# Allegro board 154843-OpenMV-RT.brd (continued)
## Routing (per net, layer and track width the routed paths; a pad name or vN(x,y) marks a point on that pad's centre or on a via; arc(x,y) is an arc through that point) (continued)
N169826: length 1.1
  TOP w0.152: U1.F13 v2(16.48,26.36)
  BOTTOM w0.152: R3.2 16.43,26.42 v2(16.48,26.36)
N229181: length 3.7
  TOP w0.254: U1.P8 22.88,22.79 23.23,22.44 v1(23.23,21.92)
  BOTTOM w0.305: v1(23.23,21.92) 23.34,21.92 23.75,21.51 C22.1 C19.1
N229229: length 12.4
  TOP w0.152: U1.P11 22.32,24.74 23.24,25.65 23.24,27.3 v2(23.75,27.81)
  BOTTOM w0.152: v2(23.75,27.81) 25.6,27.81 25.88,28.08 R8.1 R7.1 26.65,29.17 C42.1 26.97,29.77 26.97,32.11 26.81,32.27 Y1.3
N229241:
  vias: v2(20.7,17.4) v2(21.03,17.91)
N229269: length 3.5
  TOP w0.254: v2(22.86,24.39) 22.31,24.39 U1.P10
  BOTTOM w0.305: C24.1 C23.1 v2(22.86,24.39)
N229297: length 11.6
  TOP w0.152: v2(23.11,27.81) 22.86,27.56 22.86,25.81 22.11,25.06 21.68,25.06 U1.N11
  BOTTOM w0.152: v2(23.11,27.81) 23.55,27.38 25.6,27.38 26.16,27.94 27.14,27.94 27.4,28.19 R7.2 27.4,29.17 C43.1 27.54,30.08 Y1.1
N229465: length 3.7
  TOP w0.191: U1.M10 21.03,24.41 v2(21.03,25.06)
  BOTTOM w0.254: v2(21.03,25.06) 21.22,25.25 22.15,25.25 23.07,26.17 C25.1
N229469: length 9.6
  TOP w0.152: v1(25.02,20.57) 24,21.59 24,22.73 22.98,23.76 21.68,23.76 U1.N9
  BOTTOM w0.152: v1(25.02,20.57) 25.12,20.57 25.61,20.09 C44.1 27.41,20.09 27.56,19.93 Y2.1
N229477: length 8.8
  TOP w0.152: U1.K3 v2(19.73,19.21)
  BOTTOM w0.152: v2(19.73,19.21) 19.84,19.1 22.07,19.1 22.23,18.95 22.23,18.67 23.37,17.53 25.31,17.53 25.69,17.14 C46.1 R9.1
N229533: length 8.8
  TOP w0.152: v1(24.38,20.57) 23.7,21.26 23.7,22.53 22.79,23.44 U1.P9
  BOTTOM w0.152: Y2.2 27.56,20.6 27.41,20.45 26.19,20.45 25.78,20.86 C45.1 25.5,20.86 25.32,21.03 24.84,21.03 v1(24.38,20.57)
N236415:
  vias: v1(34.04,31.37) v1(34.04,30.48)
N236477: length 1.9
  TOP w0.152: J2.4 v1(30.99,27.96)
  BOTTOM w0.152: R32.1 30.97,27.94 v1(30.99,27.96)
N236509: length 6.5
  TOP w0.15: J2.3 28.98,27.3 28.9,27.23 U3.4 27.35,27.23 26.72,26.59 v2(26.46,26.59)
  BOTTOM w0.15: v2(26.46,26.59) 27.13,26.59 27.94,25.78 R11.1
N236553: length 7.5
  TOP w0.15: v2(26.46,25.96) 26.74,25.96 27.38,25.33 U3.3 27.52,26.04 27.86,26.39 28.27,26.39 28.77,26.89 29.04,26.89 29.28,26.65 J2.2
  BOTTOM w0.15: R12.1 27.14,24.76 27.61,25.23 27.61,25.64 26.99,26.26 26.7,26.26 26.46,26.03 v2(26.46,25.96)
N246574: length 11.6
  TOP w0.305: v2(18.16,34.33) 18.16,33.1 18.8,32.46 18.8,32.18 19.1,31.88 20.04,31.88 20.27,32.11 20.27,33.76 v2(20.5,33.99) ; U5.B3 v2(18.58,36.07) ; U5.A1 19.78,35.7 20.12,35.36 v2(20.12,35.31)
  BOTTOM w0.305: v2(20.5,33.99) 20.78,34.26 C59.1 20.42,34.68 20.12,34.98 v2(20.12,35.31) ; v2(18.58,36.07) 18.56,36.05 C64.1 18.56,34.74 v2(18.16,34.33) 18.03,34.21 R20.2
N246626: length 4.1
  TOP w0.188: U5.E3 17.78,39.12 17.78,39.64 18.09,39.95
  TOP w0.305: 18.09,39.95 18.14,40.01 18.92,40.01 19.94,41.02 C60.1
N246706: length 2.4
  TOP w0.152: U5.A3 18.18,35.58 17.14,34.54 C61.1
N246726: length 2.9
  TOP w0.188: U5.B2 19.38,36.07 19.38,35.13
  TOP w0.305: C62.1 19.56,34.95 19.38,35.13
N257264: length 5.3
  TOP w0.152: U6.10 5.28,22.15 5.66,21.77 6.02,21.77 6.32,22.07 6.32,22.56 6.5,22.73 8.26,22.73 8.39,22.86 C63.1
N263637: length 10.3
  TOP w0.152: R13.1 3.42,34.16 4.57,35.31 4.57,39.42 D3.2
N263641: length 6.3
  TOP w0.152: D2.2 1.31,27.64 1.46,27.48 5,27.48 5.66,28.14 RN2.8
N263645: length 4.7
  TOP w0.152: RN2.7 5.94,28.94 4.75,30.12 4.17,30.12 3.01,31.28 D2.3
N263649: length 8.1
  TOP w0.152: D2.4 1.31,32.51 1.57,32.77 3.56,32.77 3.94,32.38 3.94,30.99 4.42,30.51 5,30.51 5.77,29.74 RN2.6
N263673: length 2.3
  TOP w0.152: v1(2.67,34.54) 2.67,34.54 R13.2
  BOTTOM w0.152: Q1.3 v1(2.67,34.54)
N263791: length 4
  TOP w0.152: RN2.5 6.35,31.62 R19.1 5.04,31.62 v1(4.57,31.16)
  BOTTOM w0.152: Q1.1 v1(4.57,31.16)
N264381: length 21.1
  TOP w0.152: D1.2 D3.1
N332353: length 8.7
  TOP w0.152: v1(27.81,11.3) 27.56,11.05 26.53,11.05
  BOTTOM w0.152: R15.1 26.92,10.08 27.07,9.93 28.24,9.93 28.39,10.08 28.39,10.9 29.03,11.54 29.03,12.4 28.88,12.55 28.47,12.55 28.35,12.42 28.35,11.84 v1(27.81,11.3)
N332366: length 6.1
  TOP w0.152: v2(17.04,13) 17.27,13 17.86,13.59 U4.2
  BOTTOM w0.152: v2(17.04,13) 16.81,12.78 16.81,10.57 17.25,10.13 R16.1
N332379: length 5
  TOP w0.152: U4.3 18.16,12.32 v1(17.75,11.91)
  BOTTOM w0.152: v1(17.75,11.91) 17.37,11.91 17.22,11.76 17.22,10.79 17.4,10.62 18.31,10.62 R17.1
N332392: length 2.6
  TOP w0.152: U4.7 27.3,13.59 v1(27.81,13.08)
  BOTTOM w0.152: R18.1 27.3,13.59 v1(27.81,13.08)
N670164:
  vias: v1(22.35,2.54) v1(22.35,1.52) v1(23.37,2.54) v1(23.37,1.52)
N7344830: length 21.4
  TOP w0.152: U1.L4 20.4,19.84 21.5,19.84 21.67,19.67 21.67,19.41 21.88,19.21 22.11,19.21 22.61,18.71 22.61,14.53 22.46,14.37 21.54,14.37 21.39,14.22 21.39,13.92 21.54,13.76 22.35,13.76 22.5,13.61 22.5,13.36 22.35,13.2 21.54,13.2 21.39,13.05 21.39,12.75 21.54,12.59 21.62,12.59 21.77,12.44 21.77,12.14 21.62,11.99 21.16,11.99 21.01,11.83 21.01,11.53 21.16,11.38 21.44,11.38 21.94,10.87 24.05,10.87 24.26,10.67 24.51,10.67 24.64,10.79 v1(24.64,11.3)
  BOTTOM w0.152: v1(24.64,11.3) 24.64,11.14 24.86,10.92 25.24,10.92 26.17,11.85 R10.1

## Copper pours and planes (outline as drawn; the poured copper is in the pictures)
GND on TOP: 14.73,7.75 13.84,7.75 13.72,7.87 13.72,9.4 13.84,9.53 14.73,9.53 14.86,9.4 14.86,7.87
GND on TOP: 14.99,4.19 16.51,4.19 16.64,4.06 16.64,1.02 16.51,0.89 14.99,0.89 14.86,1.02 14.86,4.06
GND on TOP: 18.16,43.18 19.43,43.18 19.56,43.05 19.56,41.4 18.92,40.77 18.16,40.77 18.03,40.89 18.03,43.05
GND on TOP: 9.78,13.84 9.78,12.83 9.02,12.83 8.76,13.08 6.86,13.08 6.73,13.21 6.73,15.11 6.86,15.24 8.38,15.24
GND on BOTTOM: 21.72,20.83 24,20.83 24.64,20.19 25.15,20.19 25.27,20.07 25.27,19.68 25.4,19.56 26.04,19.56 26.16,19.43 26.16,18.67 26.04,18.54 25.4,18.54 24.77,19.18 23.5,19.18 23.24,19.43 20.95,19.43 20.95,19.94 21.59,19.94 21.72,20.07
GND on BOTTOM: 17.78,43.18 19.43,43.18 19.56,43.05 19.56,40.77 19.43,40.64 17.53,40.64 17.4,40.77 17.4,41.27 17.65,41.53 17.65,43.05
GND on BOTTOM: 17.53,7.37 18.92,7.37 19.05,7.24 19.05,6.1 19.3,5.84 19.3,5.08 19.18,4.95 18.41,4.95 17.4,5.97 17.4,7.24
GND on BOTTOM: 30.86,31.62 32,31.62 32.13,31.5 32.13,30.35 32,30.23 30.86,30.23 30.73,30.35 30.73,31.5
GND on BOTTOM: 18.16,17.4 20.19,17.4 20.57,17.02 20.57,15.24 20.45,15.11 17.65,15.11 17.53,15.24 17.53,16.76
GND on GND02: 0.51,0.51 0.51,42.16 2.29,43.94 5.28,43.94 4.01,45.21 4.27,45.47 31.04,45.47 31.04,43.94 33.4,43.94 35.05,42.29 35.05,0.51
VDD_3V3 on TOP: 20.19,6.22 18.92,4.95 18.92,1.02 18.8,0.89 17.65,0.89 17.53,1.02 17.53,4.45 15.11,6.86 15.11,9.4 20.19,9.4
VDD_3V3 on TOP: 7.49,12.57 9.91,12.57 10.03,12.45 10.03,11.05 9.91,10.92 7.49,10.92 7.37,11.05 7.37,12.45
VDD_3V3 on TOP: 15.49,43.18 16.89,43.18 17.02,43.05 17.02,41.53 16.89,41.4 15.49,41.4 15.37,41.53 15.37,43.05
VDD_3V3 on TOP: 25.86,15.88 27.81,15.88 27.94,15.75 27.94,14.61 27.81,14.48 25.65,14.48 25.58,14.55 25.58,15.01 25.81,15.24 25.81,15.82
VDD_3V3 on BOTTOM: 15.49,43.18 17.02,43.18 17.14,43.05 17.14,40.77 17.02,40.64 15.49,40.64 15.37,40.77 15.37,43.05
VDD_3V3 on BOTTOM: 10.03,13.28 10.03,11.56 9.91,11.43 9.02,11.43 8.89,11.56 8.89,11.94 9.14,12.19 9.14,13.28 9.17,13.31 10.01,13.31
VDD_3V3 on POWER03: 1.02,1.02 1.02,43.43 3.91,43.43 2.06,45.29 2.06,45.47 31.09,45.47 31.09,43.84 30.68,43.43 34.54,43.43 34.54,2.54 33.02,1.02 ; 1 cut-out
VDD_SOC_IN on BOTTOM: 17.02,18.67 17.02,19.46 17.09,19.53 17.09,20.19 16.97,20.32 16.51,20.32 16.38,20.45 16.38,21.46 16.26,21.59 16.26,23.88 16.38,24 17.14,24 17.27,23.88 17.27,22.86 17.4,22.73 17.53,22.73 17.65,22.61 17.65,21.84 17.53,21.72 17.53,21.08 17.65,20.95 17.91,20.95 18.29,21.34 18.54,21.34 18.67,21.21 18.67,20.45 17.78,19.56 17.78,18.47 16.59,17.27 13.46,17.27 13.34,17.4 13.34,18.03 13.46,18.16 16.51,18.16
VDD_SOC_IN on BOTTOM: 24.89,14.35 25.02,14.22 25.02,12.95 24.89,12.83 21.08,12.83 20.45,12.19 17.65,12.19 17.53,12.32 17.53,14.1 17.65,14.22 20.45,14.22 20.57,14.35
VDD_SOC_IN on POWER03: 13.36,16.92 13.36,17.73 13.41,17.78 16.66,17.78 16.92,18.03 16.92,21.46 16.74,21.64 16.31,21.64 16.28,21.67 16.28,23.9 16.38,24 18.54,24 18.67,23.88 18.67,23.11 19.3,22.48 19.3,17.53 21.08,15.75 21.08,12.83 20.95,12.7 19.23,12.7 19.13,12.8 19.13,15.67 17.93,16.87 13.41,16.87
EP on BOTTOM: 4.32,25.27 5.84,25.27 5.97,25.15 5.97,23.88 5.84,23.75 4.32,23.75 4.19,23.88 4.19,25.15
Net_2 on BOTTOM (solid shape): outline of 388 points within 71.62,0.5 75.62,91.45
Net_3 on TOP (solid shape): outline of 388 points within 71.62,0.5 75.62,91.45
Net_4 on BOTTOM (solid shape): outline of 388 points within -4.5,0.5 -0.5,91.45
Net_5 on TOP (solid shape): outline of 388 points within -4.5,0.5 -0.5,91.45
RAW_5V on BOTTOM: 21.97,3.17 21.84,3.3 21.84,4.95 24,7.11 25.27,7.11 25.4,6.99 25.4,5.71 25.65,5.46 28.57,5.46 28.96,5.84 34.8,5.84 34.92,5.71 34.92,4.19 34.8,4.06 25.02,4.06 24.13,3.17
USB_5V on TOP: 25.02,23.11 27.05,23.11 28.19,21.97 28.19,20.42 29.21,19.41 29.21,10.54 26.16,7.49 23.88,7.49 23.11,6.73 21.72,6.73 21.59,6.86 21.59,7.87 21.72,8 22.48,8 22.99,8.51 25.53,8.51 28.19,11.18 28.19,18.64 26.67,20.17 26.67,21.46 25.91,22.23 25.02,22.23 24.89,22.35 24.89,22.99
USB_5V on BOTTOM: 20.95,4.83 20.95,3.56 20.83,3.43 19.68,3.43 19.56,3.56 19.56,7.75 19.68,7.87 22.86,7.87 22.99,7.75 22.99,6.86
N229241 on TOP: 21.21,17.53 20.83,17.14 20.57,17.14 20.45,17.27 20.45,18.16 20.7,18.41 20.7,18.67 20.57,18.8 20.57,19.05 20.83,19.05 21.21,18.67
N229241 on BOTTOM: 21.72,17.27 24.89,17.27 25.02,17.14 25.02,15.88 24.89,15.75 21.08,15.75 21.08,16.64 20.45,17.27 20.45,18.03 20.57,18.16 21.21,18.16 21.34,18.03 21.34,17.65
N236415 on TOP: 31.62,32.77 34.8,32.77 34.92,32.64 34.92,22.23 34.8,22.1 31.62,22.1 31.5,22.23 31.5,32.64
N236415 on BOTTOM: 33.02,31.62 34.16,31.62 34.29,31.5 34.29,30.35 34.16,30.23 33.02,30.23 32.89,30.35 32.89,31.5
N236589 on TOP: 29.16,26.29 30.48,26.29 30.61,26.16 30.61,25.91 30.48,25.78 29.97,25.78 29.72,25.53 29.72,24.13 29.08,23.5 26.29,23.5 26.04,23.75 24.77,23.75 24.51,24 24.51,25.78 24.64,25.91 26.04,25.91 26.16,25.78 26.16,25.15 26.8,24.51 28.19,24.51 28.45,24.77 28.45,25.58
N670164 on TOP: 23.5,3.68 23.62,3.56 23.62,1.02 23.5,0.89 20.07,0.89 19.94,1.02 19.94,3.56 20.07,3.68
N670164 on BOTTOM: 23.62,1.4 23.5,1.27 20.95,1.27 20.83,1.4 20.83,2.67 20.95,2.79 23.5,2.79 23.62,2.67

Small or netless copper shapes (teardrops, artwork), in the pictures only: 2 on TOP

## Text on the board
BOTTOM: 154843-OPENMV-RT ARTWORK BOTTOM
Package Geometry/Pastemask Bottom: 154843-OPENMV-RT PASTEMASK BOTTOM
Ref Des/Silkscreen Bottom: A | VIN | P3 | 3.3V | P0 | P1 | P2 | P4 | P5 | P6 | SWO | SWC | SWD | RST | GND | CTX | FSIN | P9 | P8 | P7 | V1.0 | Built By NXP | 154843-OPENMV-RT SILKSCREEN BOTTOM
User.Comments: 154843-OPENMV-RT SOLDMASK TOP | 154843-OPENMV-RT SOLDMASK BOTTOM
TOP: 154843-OPENMV-RT ARTWORK TOP
Package Geometry/Pastemask Top: 154843-OPENMV-RT PASTEMASK TOP
Ref Des/Silkscreen Top: P0 | Pin List | P4=TXD/SCL | P5=RXD/SDA | P7=SERVO1 | P8=SERVO2 | P9=SERVO3 | P0=MOSI | P1=MISO | P2=SCLK | P6=ADC | P3=SS | GND | VIN | P1 | P2 | P3 | P4 | P5 | P6 | 3.3V | SWO | SWC | SWD | RST | CTX | FSIN | P9 | P8 | P7 | 154843-OPENMV-RT SILKSCREEN TOP
GND02: 154843-OPENMV-RT GROUND PLANE02
POWER03: 154843-OPENMV-RT POWER PLANE03
DIMENSION: 154843-OPENMV-RT DRILL CHART | 1--Gerber TOP | 2--GROUND PLANE02 | 3--POWER PLANE03 | 4--Gerber BOTTOM
COMPVAL_TYPE_TOP: LAYER 1  TOP SIDE           1 oz. | LAYER 2  INTERNAL 1      2 oz. | LAYER 3  INTERNAL 2         2 oz. | LAYER 4  BOTTOM SIDE        1 oz. | DETAIL A | LAYER STACKUP | SCALE: NONE | 24
User.9: QA | XXXX | DATE | XXXX-XX-XX | DESIGNER | UPDATE | ACTION | REVISIONS | INITIAL RELEASE | XX | REV | XXXXXX | EDADOC CODE | 86-755-88852189 | C | E | F | B | D | A | 8 | 7 | 6 | 5 | 4 | 3 | 2 | 1
User.13: FIGURE | FINISHED_SIZE | 8.0 | 30.0 | 32.0 | 40.0 | 41.0 | 100.0 | 115.0 | 22.0 | 80.0 | DRILL CHART: TOP to BOTTOM | ALL UNITS ARE IN MILS | TOLERANCE_DRILL | +0.0/-0.0 | +3.0/-3.0 | +2.0/-2.0 | PLATED | NON-PLATED | QTY | 138 | 160 | 20 | 2 | 16 | 6 | 4
